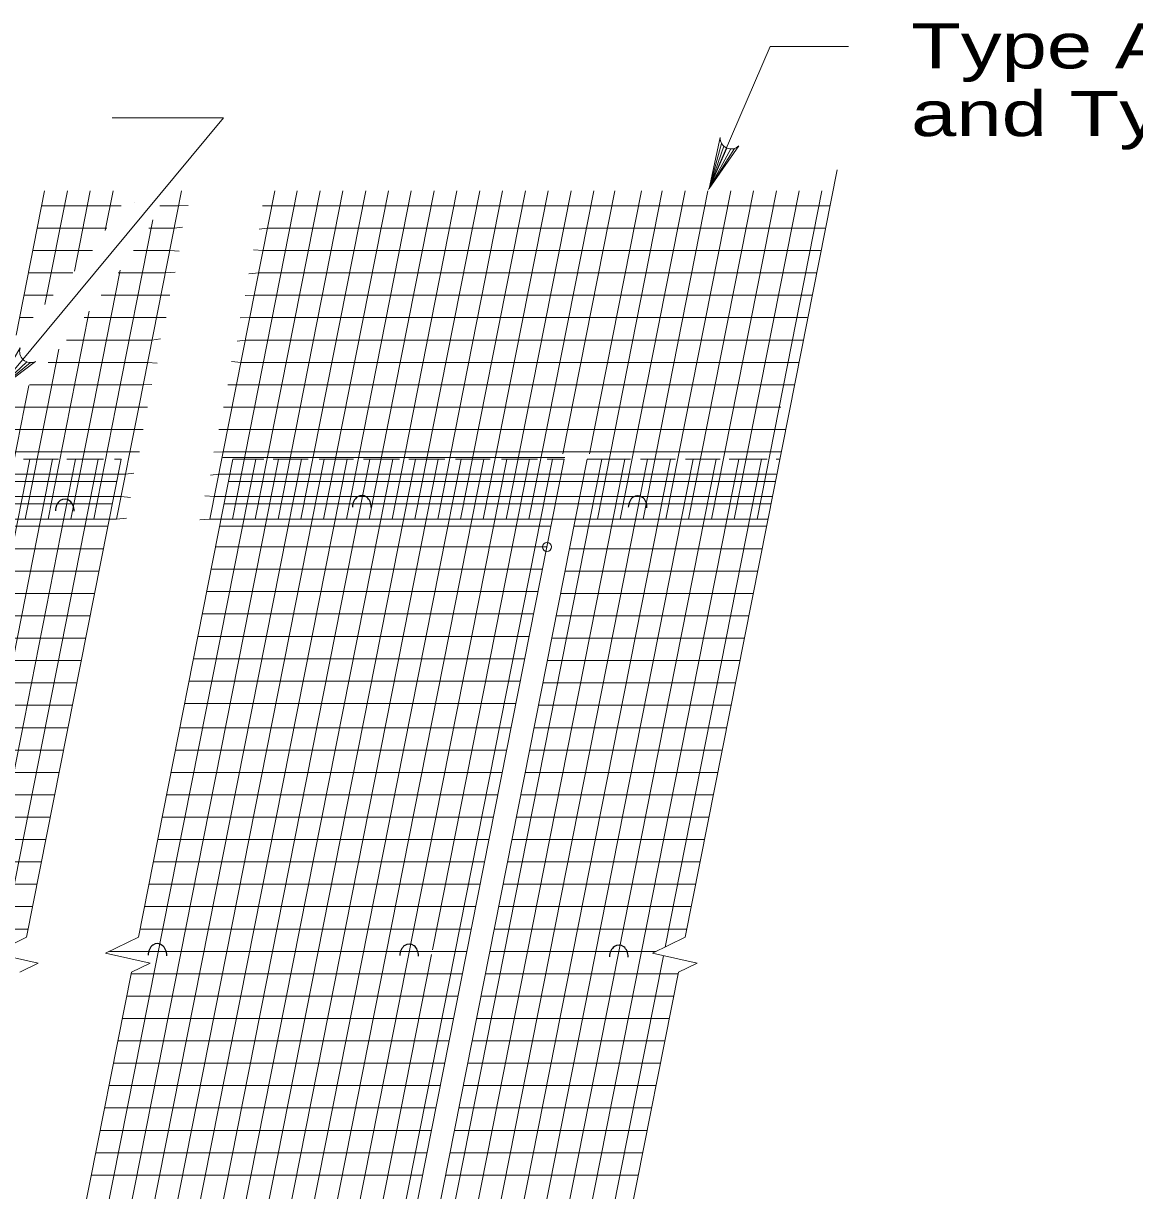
# Model space of a CAD drawing. Extents: x 1083.1 to 1117.1, y 719.4 to 741.4.
# Drawn here: x 1103.312 to 1107.154, y 728.427 to 732.465 of the extents above; entities that cross this region are included whole.
import ezdxf

# ---------------------------------------------------------------- set-up
doc = ezdxf.new("R2010")
doc.units = 0
doc.header["$LTSCALE"] = 0.062
doc.header["$PDMODE"] = 32
doc.header["$PDSIZE"] = 0.031
doc.layers.add('1', color=7, linetype='Continuous', lineweight=13)

msp = doc.modelspace()

# ---------------------------------------------------------------- linework, layer by layer
at = {"layer": '1'}
for p, q in [((1105.68042, 731.89008), (1105.89367, 732.38442)), ((1106.164, 732.38442), (1105.89367, 732.38442)), ((1103.22208, 731.19675), (1104.004, 732.13775)), ((1103.61817, 732.13775), (1104.004, 732.13775)), ((1105.72592, 732.04867), (1105.6825, 731.89283)), ((1105.73392, 732.03933), (1105.6825, 731.89283)), ((1105.74367, 732.03325), (1105.6825, 731.89283)), ((1105.76992, 732.03158), (1105.6825, 731.89283)), ((1105.758, 732.03008), (1105.6825, 731.89283)), ((1105.959, 731.11817), (1106.12483, 731.95767)), ((1103.2865, 731.3865), (1103.385, 731.88508)), ((1103.38633, 731.49258), (1103.46392, 731.88508)), ((1103.488, 731.60775), (1103.54283, 731.88508)), ((1103.59458, 731.74808), (1103.62167, 731.88508)), ((1103.7105, 731.13725), (1103.85833, 731.88508)), ((1103.95683, 730.75033), (1104.18117, 731.88508)), ((1104.03425, 730.75033), (1104.2585, 731.88508)), ((1104.11308, 730.75033), (1104.33742, 731.88508)), ((1104.192, 730.75033), (1104.41633, 731.88508)), ((1104.27083, 730.75033), (1104.49517, 731.88508)), ((1104.34975, 730.75033), (1104.57408, 731.88508)), ((1104.42867, 730.75033), (1104.65292, 731.88508)), ((1104.5075, 730.75033), (1104.73183, 731.88508)), ((1104.58642, 730.75033), (1104.81067, 731.88508)), ((1104.66525, 730.75033), (1104.88958, 731.88508)), ((1104.74417, 730.75033), (1104.96842, 731.88508)), ((1104.823, 730.75033), (1105.04733, 731.88508)), ((1104.90192, 730.75033), (1105.12625, 731.88508)), ((1104.98075, 730.75033), (1105.20508, 731.88508)), ((1105.05967, 730.75033), (1105.284, 731.88508)), ((1105.17675, 730.97617), (1105.35642, 731.88508)), ((1105.26858, 730.97617), (1105.44825, 731.88508)), ((1105.29633, 730.75033), (1105.52058, 731.88508)), ((1105.37517, 730.75033), (1105.5995, 731.88508)), ((1105.45408, 730.75033), (1105.67833, 731.88508)), ((1105.53292, 730.75033), (1105.75725, 731.88508)), ((1105.61183, 730.75033), (1105.83617, 731.88508)), ((1105.69067, 730.75033), (1105.915, 731.88508)), ((1105.76958, 730.75033), (1105.99392, 731.88508)), ((1105.84842, 730.75033), (1106.07275, 731.88508)), ((1103.65008, 731.83358), (1103.37483, 731.83358)), ((1103.69508, 731.84517), (1103.69508, 731.84525)), ((1103.84817, 731.83358), (1103.78317, 731.83358)), ((1103.84817, 731.83358), (1103.88133, 731.83408)), ((1104.13808, 731.83308), (1104.17125, 731.83358)), ((1106.09833, 731.83358), (1104.17125, 731.83358)), ((1103.63158, 731.13725), (1103.75958, 731.78458)), ((1103.59967, 731.75617), (1103.35958, 731.75617)), ((1103.83283, 731.75617), (1103.74567, 731.75617)), ((1103.83283, 731.75617), (1103.86175, 731.75975)), ((1104.127, 731.75258), (1104.15592, 731.75617)), ((1106.08308, 731.75617), (1104.15592, 731.75617)), ((1103.55017, 731.67883), (1103.34433, 731.67883)), ((1103.81758, 731.67883), (1103.69275, 731.67883)), ((1103.81758, 731.67883), (1103.85042, 731.67625)), ((1104.10775, 731.68142), (1104.14058, 731.67883)), ((1106.06775, 731.67883), (1104.14058, 731.67883)), ((1103.4825, 731.60142), (1103.329, 731.60142)), ((1103.55267, 731.13725), (1103.64642, 731.61117)), ((1103.80225, 731.60142), (1103.63933, 731.60142)), ((1103.80225, 731.60142), (1103.837, 731.60408)), ((1104.09058, 731.59875), (1104.12533, 731.60142)), ((1106.0525, 731.60142), (1104.12533, 731.60142)), ((1103.41408, 731.52408), (1103.31367, 731.52408)), ((1103.78692, 731.52408), (1103.58075, 731.52408)), ((1103.78692, 731.52408), (1103.81817, 731.5245)), ((1104.07875, 731.52367), (1104.11, 731.52408)), ((1106.03717, 731.52408), (1104.11, 731.52408)), ((1103.47383, 731.13725), (1103.5395, 731.46942)), ((1103.34525, 731.44675), (1103.29842, 731.44675)), ((1103.77167, 731.44675), (1103.52233, 731.44675)), ((1103.77167, 731.44675), (1103.80483, 731.44725)), ((1104.06158, 731.44625), (1104.09467, 731.44675)), ((1106.02192, 731.44675), (1104.09467, 731.44675)), ((1103.75633, 731.36933), (1103.46033, 731.36933)), ((1103.75633, 731.36933), (1103.78525, 731.37292)), ((1104.05058, 731.36575), (1104.07942, 731.36933)), ((1106.00667, 731.36933), (1104.07942, 731.36933)), ((1103.39492, 731.13725), (1103.4345, 731.33742)), ((1103.32408, 731.29358), (1103.20917, 731.18708)), ((1103.33592, 731.29125), (1103.20917, 731.18708)), ((1103.741, 731.292), (1103.39733, 731.292)), ((1103.74108, 731.292), (1103.77392, 731.28942)), ((1104.03133, 731.29458), (1104.06417, 731.292)), ((1105.99133, 731.292), (1104.06417, 731.292)), ((1103.31608, 731.13725), (1103.33092, 731.21208)), ((1103.72575, 731.21458), (1103.33283, 731.21458)), ((1103.72575, 731.21458), (1103.75617, 731.215)), ((1104.01842, 731.21417), (1104.04883, 731.21458)), ((1105.97608, 731.21458), (1104.04883, 731.21458)), ((1103.237, 731.13725), (1103.71033, 731.13725)), ((1103.23942, 730.75033), (1103.31592, 731.13725)), ((1103.31833, 730.75033), (1103.39475, 731.13725)), ((1103.39717, 730.75033), (1103.47367, 731.13725)), ((1103.47608, 730.75033), (1103.5525, 731.13725)), ((1103.55492, 730.75033), (1103.63142, 731.13725)), ((1103.63383, 730.75033), (1103.71033, 731.13725)), ((1103.7105, 731.13725), (1103.74083, 731.13767)), ((1105.93033, 731.13683), (1104.00308, 731.13683)), ((1105.60033, 729.30358), (1105.95883, 731.11817)), ((1103.22167, 731.05983), (1103.695, 731.05983)), ((1103.695, 731.05983), (1103.72617, 731.06025)), ((1103.98692, 731.05942), (1104.01817, 731.05983)), ((1104.018, 731.05983), (1105.94525, 731.05983)), ((1104.01817, 731.05983), (1105.20033, 731.05983)), ((1103.20642, 730.9825), (1103.67975, 730.9825)), ((1103.67975, 730.9825), (1103.71292, 730.983)), ((1103.96967, 730.982), (1104.00283, 730.9825)), ((1104.00275, 730.9825), (1105.93, 730.9825)), ((1102.78825, 727.39792), (1103.49175, 730.95708)), ((1102.83858, 728.45092), (1103.334, 730.95708)), ((1102.83867, 728.05233), (1103.41283, 730.95708)), ((1103.23542, 729.26133), (1103.57058, 730.95708)), ((1103.31158, 730.95708), (1103.4335, 730.95708)), ((1103.32267, 729.30358), (1103.6495, 730.95708)), ((1103.41092, 727.39792), (1104.11517, 730.95708)), ((1103.46217, 730.95708), (1103.58842, 730.95708)), ((1103.48983, 727.39792), (1104.19408, 730.95708)), ((1103.56867, 727.39792), (1104.27292, 730.95708)), ((1103.62633, 730.95708), (1103.6495, 730.95708)), ((1103.64758, 727.39792), (1104.35183, 730.95708)), ((1103.7095, 729.30358), (1104.03633, 730.95708)), ((1103.72642, 727.39792), (1104.43075, 730.95708)), ((1103.80533, 727.39792), (1104.50958, 730.95708)), ((1103.88425, 727.39792), (1104.5885, 730.95708)), ((1103.96308, 727.39792), (1104.66733, 730.95708)), ((1104.00142, 730.96342), (1105.18358, 730.96342)), ((1104.03633, 730.95708), (1104.14308, 730.95708)), ((1104.042, 727.39792), (1104.74625, 730.95708)), ((1104.12083, 727.39792), (1104.82508, 730.95708)), ((1104.17567, 730.95708), (1104.29667, 730.95708)), ((1104.19975, 727.39792), (1104.904, 730.95708)), ((1104.27858, 727.39792), (1104.98283, 730.95708)), ((1104.33375, 730.95708), (1104.45358, 730.95708)), ((1104.43725, 727.39792), (1105.14067, 730.95708)), ((1104.47817, 727.39792), (1105.18175, 730.95708)), ((1104.48742, 730.95708), (1104.61242, 730.95708)), ((1104.55708, 727.39792), (1105.26067, 730.95708)), ((1104.6085, 727.39792), (1105.31208, 730.95708)), ((1104.64433, 730.95708), (1104.76833, 730.95708)), ((1104.68742, 727.39792), (1105.39092, 730.95708)), ((1104.72642, 729.26017), (1105.06175, 730.95708)), ((1104.76625, 727.39792), (1105.46992, 730.95708)), ((1104.80558, 730.95708), (1104.92608, 730.95708)), ((1104.84508, 727.39792), (1105.54875, 730.95708)), ((1104.924, 727.39792), (1105.62767, 730.95708)), ((1104.96425, 730.95708), (1105.08875, 730.95708)), ((1105.00283, 727.39792), (1105.7065, 730.95708)), ((1105.08175, 727.39792), (1105.78542, 730.95708)), ((1105.12308, 730.95708), (1105.18175, 730.95708)), ((1105.26067, 730.95708), (1105.41133, 730.95708)), ((1105.445, 730.95708), (1105.56675, 730.95708)), ((1105.53067, 729.26983), (1105.86408, 730.95708)), ((1105.60042, 730.95708), (1105.72133, 730.95708)), ((1105.75242, 730.95708), (1105.88383, 730.95708)), ((1105.91408, 730.95708), (1105.92733, 730.95708)), ((1103.19108, 730.90508), (1103.66442, 730.90508)), ((1103.66442, 730.90508), (1103.69333, 730.90867)), ((1103.95858, 730.9015), (1103.9875, 730.90508)), ((1103.98742, 730.90508), (1105.91467, 730.90508)), ((1103.9875, 730.90508), (1105.16967, 730.90508)), ((1099.83433, 730.87967), (1103.63425, 730.87967)), ((1104.021, 730.87967), (1105.912, 730.87967)), ((1103.17592, 730.82775), (1103.64917, 730.82775)), ((1103.64917, 730.82775), (1103.682, 730.82517)), ((1103.93933, 730.83033), (1103.97217, 730.82775)), ((1103.97217, 730.82775), (1105.15433, 730.82775)), ((1103.97217, 730.82775), (1105.89933, 730.82775)), ((1099.81917, 730.80233), (1103.61892, 730.80233)), ((1104.00575, 730.80233), (1105.89667, 730.80233)), ((1103.16058, 730.75033), (1103.63383, 730.75033)), ((1103.63383, 730.75033), (1103.66858, 730.753)), ((1103.92208, 730.74767), (1103.95683, 730.75033)), ((1103.95683, 730.75033), (1105.139, 730.75033)), ((1103.95683, 730.75033), (1105.88408, 730.75033)), ((1103.60367, 730.725), (1101.55058, 730.725)), ((1103.99042, 730.725), (1105.13642, 730.725)), ((1105.88142, 730.725), (1105.21475, 730.725)), ((1103.97642, 730.65392), (1105.12192, 730.65392)), ((1103.58833, 730.64758), (1101.54025, 730.64758)), ((1105.86608, 730.64758), (1105.19942, 730.64758)), ((1103.96108, 730.57658), (1105.10667, 730.57658)), ((1103.573, 730.57025), (1101.48375, 730.57025)), ((1105.85083, 730.57025), (1105.18408, 730.57025)), ((1103.55775, 730.49283), (1101.43567, 730.49283)), ((1103.94575, 730.49917), (1105.09133, 730.49917)), ((1105.83558, 730.49283), (1105.16875, 730.49283)), ((1103.5425, 730.4155), (1101.38992, 730.4155)), ((1103.9305, 730.42183), (1105.076, 730.42183)), ((1105.82025, 730.4155), (1105.15342, 730.4155)), ((1103.52717, 730.33808), (1101.35017, 730.33808)), ((1103.91517, 730.34442), (1105.06075, 730.34442)), ((1105.805, 730.33808), (1105.13808, 730.33808)), ((1103.51192, 730.26075), (1101.30808, 730.26075)), ((1103.89992, 730.26708), (1105.04542, 730.26708)), ((1105.78967, 730.26075), (1105.12283, 730.26075)), ((1103.49658, 730.18333), (1101.27867, 730.18333)), ((1103.88467, 730.18967), (1105.03017, 730.18967)), ((1105.77442, 730.18333), (1105.1075, 730.18333)), ((1103.48133, 730.106), (1102.96767, 730.106)), ((1103.86933, 730.11233), (1105.01483, 730.11233)), ((1105.75908, 730.106), (1105.09217, 730.106)), ((1103.466, 730.02858), (1102.97675, 730.02858)), ((1103.853, 730.02858), (1104.9985, 730.02858)), ((1105.74375, 730.02858), (1105.07683, 730.02858)), ((1103.45067, 729.95125), (1102.97675, 729.95125)), ((1103.83767, 729.95125), (1104.98317, 729.95125)), ((1105.7285, 729.95125), (1105.0615, 729.95125)), ((1103.43542, 729.87383), (1102.97675, 729.87383)), ((1103.82233, 729.87383), (1104.96783, 729.87383)), ((1105.71317, 729.87383), (1105.04617, 729.87383)), ((1103.42008, 729.7965), (1102.98983, 729.7965)), ((1103.807, 729.7965), (1104.95258, 729.7965)), ((1105.69792, 729.7965), (1105.03083, 729.7965)), ((1103.40483, 729.71908), (1102.97675, 729.71908)), ((1103.79167, 729.71908), (1104.93725, 729.71908)), ((1105.68258, 729.71908), (1105.0155, 729.71908)), ((1103.3895, 729.64175), (1102.97675, 729.64175)), ((1103.77633, 729.64175), (1104.92192, 729.64175)), ((1105.66725, 729.64175), (1105.00017, 729.64175)), ((1103.37417, 729.56442), (1102.97675, 729.56442)), ((1103.761, 729.56442), (1104.90658, 729.56442)), ((1105.65208, 729.56442), (1104.98483, 729.56442)), ((1103.359, 729.487), (1102.97675, 729.487)), ((1103.74567, 729.487), (1104.89125, 729.487)), ((1105.63675, 729.487), (1104.9695, 729.487)), ((1103.73042, 729.40967), (1104.876, 729.40967)), ((1105.6215, 729.40967), (1104.95425, 729.40967)), ((1104.95475, 729.40967), (1105.6215, 729.40967)), ((1102.74633, 729.33225), (1103.32833, 729.33225)), ((1103.71517, 729.33225), (1104.86067, 729.33225)), ((1105.543, 729.33225), (1104.93892, 729.33225)), ((1104.9395, 729.33225), (1105.60617, 729.33225)), ((1103.32267, 729.30358), (1103.20867, 729.24833)), ((1103.7095, 729.30358), (1103.5955, 729.24833)), ((1105.60033, 729.30358), (1105.48642, 729.24833)), ((1103.60908, 729.25492), (1104.84483, 729.25492)), ((1104.3575, 727.39792), (1104.72308, 729.24375)), ((1105.49992, 729.25492), (1104.92358, 729.25492)), ((1105.16058, 727.39792), (1105.52467, 729.24)), ((1103.33208, 727.39792), (1103.68575, 729.18333)), ((1103.68458, 729.1775), (1104.83008, 729.1775)), ((1105.57542, 729.1775), (1104.90825, 729.1775)), ((1105.22425, 727.40017), (1105.57658, 729.18333)), ((1103.66925, 729.10017), (1104.81475, 729.10017)), ((1104.89358, 729.10017), (1105.56008, 729.10017)), ((1103.65392, 729.02275), (1104.79942, 729.02275)), ((1104.87825, 729.02275), (1105.545, 729.02275)), ((1103.63858, 728.94542), (1104.78408, 728.94542)), ((1104.863, 728.94542), (1105.52967, 728.94542)), ((1103.62325, 728.868), (1104.76883, 728.868)), ((1104.84767, 728.868), (1105.51433, 728.868)), ((1103.60792, 728.79067), (1104.7535, 728.79067)), ((1104.83233, 728.79067), (1105.49908, 728.79067)), ((1103.59258, 728.71325), (1104.73817, 728.71325)), ((1104.81708, 728.71325), (1105.48383, 728.71325)), ((1103.57725, 728.63592), (1104.72283, 728.63592)), ((1104.80175, 728.63592), (1105.46858, 728.63592)), ((1103.56192, 728.5585), (1104.7075, 728.5585)), ((1104.78642, 728.5585), (1105.45325, 728.5585)), ((1103.54658, 728.48117), (1104.69217, 728.48117)), ((1104.77125, 728.48117), (1105.43792, 728.48117))]:
    msp.add_line(p, q, dxfattribs=at)
for points in [[(1105.78567, 732.041), (1105.6825, 731.89283), (1105.72075, 732.06925)], [(1103.35375, 731.29525), (1103.20917, 731.18708), (1103.30108, 731.3425)], [(1101.88275, 729.40967), (1101.1665, 729.40967), (1103.34367, 729.40967)], [(1103.20867, 729.24833), (1103.36333, 729.21458), (1103.29892, 729.18333)], [(1103.5955, 729.24833), (1103.75008, 729.21458), (1103.68575, 729.18333)], [(1105.48642, 729.24833), (1105.641, 729.21458), (1105.57658, 729.18333)]]:
    msp.add_lwpolyline(points, dxfattribs=at)
for centre, start, end in [((1105.75885, 732.06823), 178.54875, 314.37488), ((1103.33691, 731.32953), 160.19314, 296.01927)]:
    msp.add_arc(centre, 0.0382, start, end, dxfattribs=at)
at = {"layer": '1', "lineweight": 25}
for centre in [(1103.45464, 730.77798), (1104.48174, 730.79081), (1105.43546, 730.79006), (1103.77499, 729.2407), (1104.64525, 729.23945), (1105.37024, 729.23579)]:
    msp.add_ellipse(centre, major_axis=(0.00099, 0.04097), ratio=0.78812, start_param=4.7123995, end_param=7.8539922, dxfattribs=at)
at = {"layer": '1'}
msp.add_point((1105.12192, 730.65392), dxfattribs=at)

# ---------------------------------------------------------------- texts
at = {"layer": '1', "width": 1.35}
for s, p in [('Type A-F', (1106.38083, 732.30858)), ('and Type H-I', (1106.38083, 732.07458))]:
    msp.add_text(s, height=0.156, dxfattribs=at).set_placement(p)

doc.saveas('drawing.dxf')
